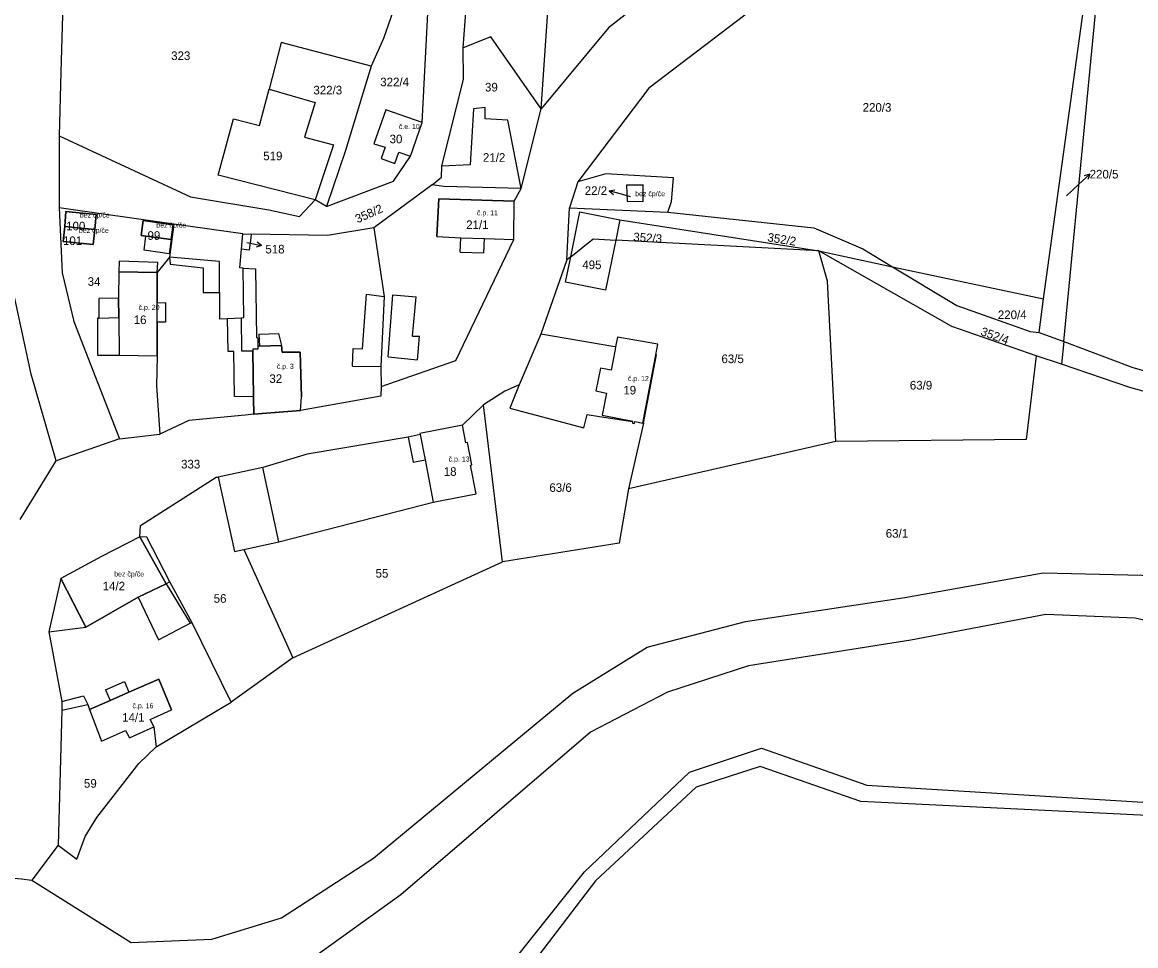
# Model space of a CAD drawing. Extents: x -880531 to -877616, y -1023932 to -1021350.
# Drawn here: x -878781.4 to -878561.2, y -1022509.8 to -1022327.2 of the extents above; entities that cross this region are included whole.
import ezdxf

# ---------------------------------------------------------------- set-up
doc = ezdxf.new("R2010")
doc.units = 0
for name, color, linetype in [('Definiční body', 7, 'Continuous'), ('Hranice parcel', 7, 'Continuous'), ('Parcelní čísla', 7, 'Continuous'), ('Polygon budovy', 7, 'Continuous'), ('Pop  PČ popisy', 7, 'Continuous'), ('Vnitřní kresba', 7, 'Continuous')]:
    doc.layers.add(name, color=color, linetype=linetype)

msp = doc.modelspace()

# ---------------------------------------------------------------- linework, layer by layer
at = {"layer": 'Hranice parcel'}
for p, q in [((-878579.47, -1022381.89), (-878569.16, -1022307.52)), ((-878702.35, -1022346.99), (-878701.15, -1022324.12)), ((-878694.27, -1022332.2), (-878693.64, -1022324.29)), ((-878682.77, -1022360.06), (-878678.8, -1022344.27)), ((-878704.66, -1022353.65), (-878702.35, -1022346.99)), ((-878774.14, -1022349.64), (-878774.16, -1022363.87)), ((-878700.4, -1022359.3), (-878711.92, -1022367.79)), ((-878671.6, -1022358.7), (-878673.23, -1022363.89)), ((-878721.25, -1022363.62), (-878723.5, -1022362.26)), ((-878751.45, -1022367.12), (-878774.16, -1022363.87)), ((-878673.72, -1022374.12), (-878673.23, -1022363.89)), ((-878673.23, -1022363.89), (-878653.77, -1022364.73)), ((-878773.06, -1022367.58), (-878767.11, -1022368.17)), ((-878737.82, -1022369.02), (-878751.45, -1022367.12)), ((-878663.25, -1022366.24), (-878664.07, -1022370.25)), ((-878663.25, -1022366.24), (-878623.93, -1022372.37)), ((-878738.07, -1022372.03), (-878737.82, -1022369.02)), ((-878737.82, -1022369.02), (-878736.18, -1022369.05)), ((-878736.18, -1022369.05), (-878736.26, -1022369.77)), ((-878623.93, -1022372.37), (-878664.07, -1022370.25)), ((-878738.41, -1022375.74), (-878738.07, -1022372.03)), ((-878623.93, -1022372.37), (-878609.33, -1022375.5)), ((-878673.72, -1022374.12), (-878678.87, -1022388.85)), ((-878672.98, -1022373.54), (-878673.72, -1022374.12)), ((-878609.33, -1022375.5), (-878579.47, -1022381.89)), ((-878580.3, -1022388.5), (-878579.47, -1022381.89)), ((-878678.87, -1022388.85), (-878683.16, -1022398.86)), ((-878655.76, -1022390.85), (-878663.73, -1022389.44)), ((-878580.3, -1022388.5), (-878575.47, -1022390.32)), ((-878575.47, -1022390.32), (-878575.9, -1022394.81)), ((-878575.9, -1022394.81), (-878580.9, -1022393.1)), ((-878735.65, -1022404.69), (-878735.69, -1022401.58)), ((-878690.21, -1022402.82), (-878694.41, -1022406.84)), ((-878686.48, -1022433.85), (-878690.21, -1022402.82)), ((-878658.6, -1022406.44), (-878661.53, -1022419.4)), ((-878762.25, -1022409.56), (-878774.74, -1022413.92)), ((-878762.25, -1022409.56), (-878754.24, -1022408.64)), ((-878620.57, -1022410.08), (-878661.53, -1022419.4)), ((-878781.84, -1022425.46), (-878774.74, -1022413.92)), ((-878737.66, -1022431.41), (-878727.94, -1022452.85)), ((-878727.94, -1022452.85), (-878686.48, -1022433.85)), ((-878727.94, -1022452.85), (-878740.13, -1022461.62)), ((-878754.97, -1022470.47), (-878740.13, -1022461.62)), ((-878773.64, -1022463.22), (-878774.32, -1022489.89)), ((-878774.32, -1022489.89), (-878779.59, -1022496.84))]:
    msp.add_line(p, q, dxfattribs=at)
for points in [[(-878589.21, -1022285.43), (-878614.84, -1022293.57), (-878633.22, -1022303.64), (-878648.06, -1022314.55), (-878665.5, -1022328.26), (-878678.8, -1022344.27)], [(-878678.8, -1022344.27), (-878675.7, -1022298.99), (-878693.21, -1022298.36)], [(-878772.79, -1022301.21), (-878773.84, -1022336.98), (-878774.14, -1022349.64)], [(-878609.56, -1022306.45), (-878614.79, -1022308.53), (-878635.51, -1022323.46), (-878657.51, -1022340.21), (-878671.6, -1022358.7)], [(-878575.47, -1022390.32), (-878567.58, -1022308.88), (-878569.16, -1022307.52)], [(-878707.2, -1022322.19), (-878709.98, -1022330.39), (-878712.42, -1022335.85)], [(-878678.8, -1022344.27), (-878688.78, -1022330.06), (-878694.27, -1022332.2)], [(-878712.42, -1022335.85), (-878730.27, -1022331.16), (-878732.62, -1022340.37)], [(-878698.46, -1022355.64), (-878694.2, -1022338.41), (-878694.27, -1022332.2)], [(-878712.42, -1022335.85), (-878717.5, -1022352.55), (-878721.25, -1022363.62)], [(-878723.5, -1022362.26), (-878742.72, -1022357.39), (-878739.68, -1022346.27), (-878734.53, -1022347.6), (-878732.62, -1022340.37)], [(-878732.62, -1022340.37), (-878723.52, -1022343.02), (-878725.66, -1022349.9), (-878719.9, -1022351.4), (-878723.5, -1022362.26)], [(-878702.35, -1022346.99), (-878709.57, -1022344.49), (-878711.91, -1022351.24), (-878709.69, -1022351.87), (-878710.48, -1022354.13), (-878707.77, -1022355.09), (-878706.97, -1022352.83), (-878704.66, -1022353.65)], [(-878682.77, -1022360.06), (-878685.43, -1022346.56), (-878689.88, -1022346.24), (-878689.9, -1022344.05), (-878692.19, -1022344.27), (-878692.85, -1022355.38), (-878698.46, -1022355.64)], [(-878774.14, -1022349.64), (-878748.17, -1022361.68), (-878732.67, -1022364.28), (-878726.64, -1022365.58), (-878723.5, -1022362.26)], [(-878721.25, -1022363.62), (-878708.06, -1022358.58), (-878704.66, -1022353.65)], [(-878700.4, -1022359.3), (-878698.51, -1022357.81), (-878698.46, -1022355.64)], [(-878653.77, -1022364.73), (-878653.07, -1022362.63), (-878652.68, -1022357.96), (-878666.04, -1022357.13), (-878671.6, -1022358.7)], [(-878682.77, -1022360.06), (-878698.08, -1022359.62), (-878700.4, -1022359.3)], [(-878710.46, -1022399.17), (-878695.68, -1022394.04), (-878684.22, -1022370.1), (-878684.16, -1022362.54), (-878682.77, -1022360.06)], [(-878774.16, -1022363.87), (-878773.56, -1022376.72), (-878771.27, -1022386.32), (-878762.25, -1022409.56)], [(-878773.06, -1022367.58), (-878772.81, -1022364.57), (-878766.82, -1022365.19), (-878767.11, -1022368.17)], [(-878672.98, -1022373.54), (-878671.2, -1022364.68), (-878663.25, -1022366.24)], [(-878653.77, -1022364.73), (-878624.87, -1022367.81), (-878615.19, -1022371.96), (-878609.33, -1022375.5)], [(-878767.11, -1022368.17), (-878767.41, -1022371.13), (-878773.34, -1022370.55), (-878773.06, -1022367.58)], [(-878757.35, -1022372.26), (-878756.99, -1022369.47), (-878757.92, -1022369.34), (-878757.52, -1022366.4), (-878751.61, -1022367.2), (-878752.01, -1022370.15), (-878752.39, -1022372.93), (-878757.35, -1022372.26)], [(-878751.45, -1022367.12), (-878752.35, -1022373.6), (-878754.77, -1022376.64)], [(-878711.92, -1022367.79), (-878721.1, -1022369.31), (-878736.18, -1022369.05)], [(-878711.92, -1022367.79), (-878709.9, -1022381.4), (-878710.51, -1022395.25), (-878710.46, -1022399.17)], [(-878774.74, -1022413.92), (-878779.71, -1022396.76), (-878785.9, -1022368.31)], [(-878736.26, -1022369.77), (-878736.56, -1022372.22), (-878738.07, -1022372.03)], [(-878664.07, -1022370.25), (-878666.08, -1022380.13), (-878673.99, -1022378.57), (-878672.98, -1022373.54)], [(-878620.57, -1022410.08), (-878622.18, -1022378.35), (-878623.93, -1022372.37)], [(-878580.9, -1022393.1), (-878597.59, -1022387.36), (-878623.93, -1022372.37)], [(-878754.77, -1022376.64), (-878754.67, -1022374.69), (-878762.26, -1022374.38), (-878762.32, -1022376.51), (-878762.39, -1022381.73), (-878766.33, -1022381.81), (-878766.34, -1022385.67)], [(-878738.06, -1022385.61), (-878737.65, -1022385.58), (-878737.77, -1022375.77), (-878738.41, -1022375.74)], [(-878609.33, -1022375.5), (-878596.58, -1022383.19), (-878582.14, -1022388.34), (-878580.3, -1022388.5)], [(-878766.34, -1022385.67), (-878766.59, -1022385.68), (-878766.55, -1022392.97), (-878762.28, -1022392.97), (-878754.76, -1022393.13), (-878754.89, -1022399.07), (-878754.24, -1022408.64)], [(-878735.69, -1022401.58), (-878735.69, -1022401.22), (-878735.88, -1022392.18), (-878738.02, -1022392.21), (-878738.06, -1022385.61)], [(-878663.73, -1022389.44), (-878664.11, -1022391.37), (-878664.66, -1022391.26), (-878678.87, -1022388.85)], [(-878658.6, -1022406.44), (-878655.98, -1022392.95), (-878656.15, -1022392.92), (-878655.76, -1022390.85)], [(-878575.47, -1022390.32), (-878561.81, -1022395.45), (-878519.45, -1022407.53), (-878480.63, -1022419.65)], [(-878580.9, -1022393.1), (-878582.9, -1022409.7), (-878620.57, -1022410.08)], [(-878431.64, -1022431.71), (-878476.27, -1022424.65), (-878519.53, -1022411.25), (-878562.4, -1022399.42), (-878575.9, -1022394.81)], [(-878683.16, -1022398.86), (-878686.03, -1022400.1), (-878690.21, -1022402.82)], [(-878683.16, -1022398.86), (-878685.01, -1022403.45), (-878670.39, -1022407.34), (-878669.75, -1022404.74), (-878667.29, -1022405.12), (-878660.73, -1022406.12), (-878660.79, -1022406.45)], [(-878710.46, -1022399.17), (-878710.55, -1022401.12), (-878726.45, -1022403.91), (-878735.65, -1022404.69)], [(-878735.65, -1022404.69), (-878737.39, -1022404.84), (-878748.51, -1022405.92), (-878754.24, -1022408.64)], [(-878694.41, -1022406.84), (-878702.8, -1022408.5), (-878702.76, -1022408.7), (-878705.12, -1022409.2), (-878725.11, -1022412.6), (-878733.89, -1022415.18), (-878742.68, -1022417.1)], [(-878737.66, -1022431.41), (-878730.68, -1022429.88), (-878700.15, -1022422.09), (-878691.7, -1022420.39), (-878692.82, -1022414.77), (-878692.53, -1022414.71), (-878693.41, -1022410.28), (-878693.71, -1022410.34), (-878694.41, -1022406.84)], [(-878660.79, -1022406.45), (-878660.36, -1022406.53), (-878660.28, -1022406.13)], [(-878660.28, -1022406.13), (-878658.73, -1022406.42), (-878658.6, -1022406.44)], [(-878758.2, -1022428.9), (-878758.09, -1022426.66), (-878743.07, -1022417.09), (-878742.68, -1022417.1)], [(-878742.68, -1022417.1), (-878739.45, -1022431.81), (-878737.66, -1022431.41)], [(-878661.53, -1022419.4), (-878663.38, -1022430.17), (-878686.48, -1022433.85)], [(-878758.2, -1022428.9), (-878765.76, -1022432.82), (-878773.82, -1022437.14)], [(-878752.28, -1022437.82), (-878756.8, -1022428.96), (-878758.2, -1022428.9)], [(-878779.59, -1022496.84), (-878759.93, -1022509.12), (-878743.95, -1022508.49), (-878730.15, -1022504.28), (-878711.96, -1022492.47), (-878672.55, -1022459.82), (-878657.85, -1022450.75), (-878638.42, -1022445.65), (-878606.87, -1022440.92), (-878579.56, -1022436.07), (-878560.03, -1022436.51), (-878534.07, -1022443.31), (-878452.29, -1022470.77)], [(-878773.82, -1022437.14), (-878776.19, -1022447.68), (-878773.63, -1022461.46), (-878773.64, -1022463.22)], [(-878752.28, -1022437.82), (-878753.01, -1022438.21), (-878758.51, -1022440.87), (-878768.9, -1022446.76), (-878773.82, -1022437.14)], [(-878740.13, -1022461.62), (-878747.87, -1022445.95), (-878752.28, -1022437.82)], [(-878108.11, -1022440.58), (-878152.15, -1022446.77), (-878167.86, -1022449.63), (-878217.16, -1022451.24), (-878301.33, -1022453.9), (-878333.67, -1022456.67), (-878366.21, -1022467.52), (-878407.13, -1022480.7), (-878435.64, -1022482.95), (-878455.12, -1022478.73), (-878537.04, -1022450.63), (-878561.34, -1022444.97), (-878578.99, -1022444.28), (-878605.69, -1022449.33), (-878637.81, -1022454.4), (-878653.86, -1022459.64), (-878669.06, -1022467.56), (-878706.56, -1022499.73), (-878724.15, -1022512.39), (-878736.44, -1022518.55), (-878757.9, -1022522.41)], [(-878773.64, -1022463.22), (-878768.49, -1022462.07), (-878768.18, -1022463.09), (-878765.77, -1022469.3), (-878761.06, -1022467.24), (-878760.21, -1022468.65), (-878755.46, -1022466.52), (-878754.97, -1022470.47)], [(-878774.32, -1022489.89), (-878770.65, -1022492.64), (-878769.02, -1022488.2), (-878766.68, -1022484.39), (-878758.38, -1022473.74), (-878754.97, -1022470.47)], [(-878757.9, -1022522.41), (-878743.38, -1022532.72), (-878730.23, -1022539.4), (-878709.85, -1022535.98), (-878694.32, -1022525.35), (-878670.27, -1022495.13), (-878649.48, -1022475.44), (-878635.27, -1022470.68), (-878614.41, -1022478.04), (-878543.73, -1022482.35), (-878506.92, -1022500.7), (-878475.11, -1022508.02), (-878399.08, -1022508.59), (-878373.94, -1022502.74), (-878346.19, -1022490.2), (-878334.94, -1022490.41), (-878279.22, -1022499.74), (-878220.51, -1022507.42), (-878194.43, -1022507.39), (-878145.84, -1022503.8), (-878124.82, -1022500.78)], [(-878125.35, -1022504.99), (-878146.35, -1022507.21), (-878194.02, -1022510.96), (-878220.76, -1022511.05), (-878280.27, -1022503.97), (-878335.4, -1022493.58), (-878344.86, -1022493.55), (-878371.73, -1022505.4), (-878399.1, -1022512.43), (-878475.7, -1022511.16), (-878508.77, -1022503.35), (-878545.47, -1022484.68), (-878615.6, -1022481.24), (-878635.5, -1022474.3), (-878648.14, -1022478.45), (-878668.08, -1022496.96), (-878691.68, -1022527.88), (-878708.19, -1022539.68), (-878731.2, -1022543.61), (-878748.07, -1022535.1), (-878763.51, -1022523.14)], [(-878789.71, -1022495.74), (-878787.92, -1022495.97), (-878781.61, -1022496.55), (-878779.59, -1022496.84)]]:
    msp.add_lwpolyline(points, dxfattribs=at)
at = {"layer": 'Polygon budovy'}
for points in [[(-878702.35, -1022346.99), (-878709.57, -1022344.49), (-878711.91, -1022351.24), (-878709.69, -1022351.87), (-878710.48, -1022354.13), (-878707.77, -1022355.09), (-878706.97, -1022352.83), (-878704.66, -1022353.65)], [(-878661.94, -1022359.37), (-878661.83, -1022362.54), (-878658.67, -1022362.63), (-878658.62, -1022359.35)], [(-878684.22, -1022370.1), (-878684.16, -1022362.54), (-878699.03, -1022362.08), (-878699.48, -1022369.54), (-878694.74, -1022369.8), (-878690.06, -1022369.93)], [(-878772.81, -1022364.57), (-878773.06, -1022367.58), (-878767.11, -1022368.17), (-878766.82, -1022365.19)], [(-878773.34, -1022370.55), (-878767.41, -1022371.13), (-878767.11, -1022368.17), (-878773.06, -1022367.58)], [(-878757.92, -1022369.34), (-878756.99, -1022369.47), (-878752.01, -1022370.15), (-878751.61, -1022367.2), (-878757.52, -1022366.4)], [(-878754.77, -1022386.5), (-878754.77, -1022382.62), (-878754.77, -1022376.64), (-878762.32, -1022376.51), (-878762.39, -1022381.73), (-878762.35, -1022385.53), (-878762.28, -1022392.97), (-878754.76, -1022393.13)], [(-878664.11, -1022391.37), (-878664.21, -1022391.9), (-878665.01, -1022395.96), (-878667.1, -1022395.55), (-878667.99, -1022400.08), (-878665.89, -1022400.49), (-878666.75, -1022404.86), (-878660.71, -1022406.04), (-878660.73, -1022406.12), (-878660.79, -1022406.45), (-878660.36, -1022406.53), (-878660.28, -1022406.13), (-878658.73, -1022406.42), (-878656.23, -1022393.32), (-878656.15, -1022392.92), (-878655.76, -1022390.85), (-878663.73, -1022389.44)], [(-878726.45, -1022403.91), (-878726.25, -1022401.24), (-878726.48, -1022392.42), (-878730.07, -1022392.4), (-878730.15, -1022391.08), (-878734.55, -1022391.24), (-878734.88, -1022391.25), (-878734.88, -1022391.82), (-878735.87, -1022391.84), (-878735.88, -1022392.18), (-878735.69, -1022401.22), (-878735.69, -1022401.58), (-878735.65, -1022404.69)], [(-878702.76, -1022408.7), (-878701.78, -1022413.71), (-878700.15, -1022422.09), (-878691.7, -1022420.39), (-878692.82, -1022414.77), (-878692.53, -1022414.71), (-878693.41, -1022410.28), (-878693.71, -1022410.34), (-878694.41, -1022406.84), (-878702.8, -1022408.5)], [(-878773.82, -1022437.14), (-878768.9, -1022446.76), (-878758.51, -1022440.87), (-878753.01, -1022438.21), (-878758.2, -1022428.9), (-878765.76, -1022432.82)], [(-878768.18, -1022463.09), (-878765.77, -1022469.3), (-878761.06, -1022467.24), (-878760.21, -1022468.65), (-878755.46, -1022466.52), (-878756.15, -1022465.01), (-878751.92, -1022463.1), (-878754.47, -1022457.09), (-878760.35, -1022459.64), (-878764.05, -1022461.31)]]:
    msp.add_lwpolyline(points, close=True, dxfattribs=at)
at = {"layer": 'Pop  PČ popisy'}
for p, q in [((-878574.9, -1022361.49), (-878572.53, -1022359.26)), ((-878572.53, -1022359.26), (-878570.335, -1022357.213)), ((-878570.335, -1022357.213), (-878571.409, -1022357.53)), ((-878570.335, -1022357.213), (-878570.726, -1022358.263)), ((-878665.345, -1022360.483), (-878664.244, -1022360.278)), ((-878662.46, -1022361.31), (-878665.345, -1022360.483)), ((-878665.345, -1022360.483), (-878664.52, -1022361.24)), ((-878661.18, -1022361.69), (-878662.46, -1022361.31)), ((-878737.06, -1022370.75), (-878734.114, -1022371.323)), ((-878734.114, -1022371.323), (-878735.193, -1022371.623)), ((-878734.114, -1022371.323), (-878735.002, -1022370.64))]:
    msp.add_line(p, q, dxfattribs=at)
at = {"layer": 'Vnitřní kresba'}
for p, q in [((-878661.94, -1022359.37), (-878658.62, -1022359.35)), ((-878658.67, -1022362.63), (-878658.62, -1022359.35)), ((-878661.94, -1022359.37), (-878661.83, -1022362.54)), ((-878699.48, -1022369.54), (-878699.03, -1022362.08)), ((-878699.03, -1022362.08), (-878684.16, -1022362.54)), ((-878661.83, -1022362.54), (-878658.67, -1022362.63)), ((-878752.01, -1022370.15), (-878756.99, -1022369.47)), ((-878699.48, -1022369.54), (-878694.74, -1022369.8)), ((-878694.86, -1022372.64), (-878694.74, -1022369.8)), ((-878694.74, -1022369.8), (-878690.06, -1022369.93)), ((-878690.14, -1022372.77), (-878690.06, -1022369.93)), ((-878690.06, -1022369.93), (-878684.22, -1022370.1)), ((-878672.98, -1022373.54), (-878668.52, -1022370.02)), ((-878668.52, -1022370.02), (-878664.07, -1022370.25)), ((-878742.44, -1022374.45), (-878752.35, -1022373.6)), ((-878752.35, -1022373.6), (-878752.2, -1022375.03)), ((-878742.45, -1022380.62), (-878742.44, -1022374.45)), ((-878694.86, -1022372.64), (-878690.14, -1022372.77)), ((-878762.32, -1022376.51), (-878754.77, -1022376.64)), ((-878754.77, -1022376.64), (-878754.77, -1022382.62)), ((-878752.2, -1022375.03), (-878745.67, -1022375.76)), ((-878745.67, -1022375.76), (-878745.66, -1022380.64)), ((-878737.77, -1022375.77), (-878735.29, -1022375.9)), ((-878735.29, -1022375.9), (-878735.1, -1022389.53)), ((-878745.66, -1022380.64), (-878742.45, -1022380.62)), ((-878742.45, -1022380.62), (-878742.45, -1022385.82)), ((-878714.17, -1022391.77), (-878713.34, -1022380.96)), ((-878713.34, -1022380.96), (-878709.9, -1022381.4)), ((-878709.09, -1022393.36), (-878708.14, -1022381.07)), ((-878708.14, -1022381.07), (-878703.55, -1022381.44)), ((-878762.35, -1022385.53), (-878762.39, -1022381.73)), ((-878754.77, -1022382.62), (-878753.15, -1022382.61)), ((-878754.77, -1022386.5), (-878754.77, -1022382.62)), ((-878753.15, -1022382.61), (-878753.13, -1022386.49)), ((-878704.25, -1022389.21), (-878703.55, -1022381.44)), ((-878766.34, -1022385.67), (-878762.35, -1022385.53)), ((-878762.35, -1022385.53), (-878762.28, -1022392.97)), ((-878742.45, -1022385.82), (-878740.84, -1022385.74)), ((-878740.84, -1022385.74), (-878738.06, -1022385.61)), ((-878740.75, -1022392.29), (-878740.84, -1022385.74)), ((-878753.13, -1022386.49), (-878754.77, -1022386.5)), ((-878754.77, -1022386.5), (-878754.76, -1022393.13)), ((-878735.1, -1022389.53), (-878734.89, -1022389.58)), ((-878734.89, -1022389.58), (-878734.88, -1022391.25)), ((-878734.63, -1022388.85), (-878730.75, -1022388.71)), ((-878734.63, -1022388.85), (-878734.55, -1022391.24)), ((-878730.75, -1022388.71), (-878730.15, -1022391.08)), ((-878704.25, -1022389.21), (-878702.89, -1022389.25)), ((-878703.26, -1022393.93), (-878702.89, -1022389.25)), ((-878739.59, -1022392.26), (-878740.75, -1022392.29)), ((-878739.45, -1022401.17), (-878739.59, -1022392.26)), ((-878735.87, -1022391.84), (-878735.88, -1022392.18)), ((-878734.88, -1022391.82), (-878735.87, -1022391.84)), ((-878734.55, -1022391.24), (-878734.88, -1022391.25)), ((-878734.88, -1022391.25), (-878734.88, -1022391.82)), ((-878734.55, -1022391.24), (-878730.15, -1022391.08)), ((-878730.15, -1022391.08), (-878730.07, -1022392.4)), ((-878730.07, -1022392.4), (-878726.48, -1022392.42)), ((-878716.15, -1022395.16), (-878716.01, -1022391.68)), ((-878716.01, -1022391.68), (-878714.17, -1022391.77)), ((-878664.21, -1022391.9), (-878665.01, -1022395.96)), ((-878664.11, -1022391.37), (-878664.21, -1022391.9)), ((-878726.48, -1022392.42), (-878726.25, -1022401.24)), ((-878709.09, -1022393.36), (-878703.26, -1022393.93)), ((-878658.73, -1022406.42), (-878656.23, -1022393.32)), ((-878656.23, -1022393.32), (-878656.15, -1022392.92)), ((-878716.15, -1022395.16), (-878710.51, -1022395.25)), ((-878667.1, -1022395.55), (-878667.99, -1022400.08)), ((-878665.01, -1022395.96), (-878667.1, -1022395.55)), ((-878735.69, -1022401.22), (-878739.45, -1022401.17)), ((-878667.99, -1022400.08), (-878665.89, -1022400.49)), ((-878665.89, -1022400.49), (-878666.75, -1022404.86)), ((-878726.45, -1022403.91), (-878726.25, -1022401.24)), ((-878666.75, -1022404.86), (-878660.71, -1022406.04)), ((-878660.71, -1022406.04), (-878660.73, -1022406.12)), ((-878705.12, -1022409.2), (-878704.15, -1022414.17)), ((-878702.76, -1022408.7), (-878701.78, -1022413.71)), ((-878704.15, -1022414.17), (-878701.78, -1022413.71)), ((-878701.78, -1022413.71), (-878700.15, -1022422.09)), ((-878730.68, -1022429.88), (-878733.89, -1022415.18)), ((-878758.2, -1022428.9), (-878753.01, -1022438.21)), ((-878753.01, -1022438.21), (-878748.24, -1022445.98)), ((-878758.51, -1022440.87), (-878754.48, -1022449.28)), ((-878776.19, -1022447.68), (-878768.9, -1022446.76)), ((-878754.48, -1022449.28), (-878748.24, -1022445.98)), ((-878748.24, -1022445.98), (-878747.87, -1022445.95)), ((-878764.98, -1022459.15), (-878761.26, -1022457.53)), ((-878761.26, -1022457.53), (-878760.35, -1022459.64)), ((-878760.35, -1022459.64), (-878754.47, -1022457.09)), ((-878754.47, -1022457.09), (-878751.92, -1022463.1)), ((-878773.63, -1022461.46), (-878769.37, -1022460.39)), ((-878769.37, -1022460.39), (-878768.49, -1022462.07)), ((-878764.98, -1022459.15), (-878764.05, -1022461.31)), ((-878764.05, -1022461.31), (-878760.35, -1022459.64)), ((-878768.18, -1022463.09), (-878764.05, -1022461.31)), ((-878756.15, -1022465.01), (-878751.92, -1022463.1)), ((-878756.15, -1022465.01), (-878755.46, -1022466.52))]:
    msp.add_line(p, q, dxfattribs=at)

# ---------------------------------------------------------------- texts
at = {"layer": 'Definiční body'}
for s, p in [('č.e. 10', (-878706.98, -1022348.28)), ('bez čp/če', (-878660.23, -1022361.57)), ('bez čp/če', (-878770.06, -1022365.8)), ('č.p. 11', (-878691.52, -1022365.35)), ('bez čp/če', (-878770.24, -1022368.82)), ('bez čp/če', (-878754.94, -1022367.79)), ('č.p. 20', (-878758.45, -1022384.05)), ('č.p. 3', (-878731.13, -1022395.7)), ('č.p. 12', (-878661.67, -1022398.12)), ('č.p. 13', (-878697.13, -1022414.04)), ('bez čp/če', (-878763.27, -1022436.76)), ('č.p. 16', (-878759.65, -1022462.81))]:
    msp.add_text(s, height=1, dxfattribs=at).set_placement(p)
at = {"layer": 'Parcelní čísla'}
for s, p in [('323', (-878752, -1022334.64)), ('322/4', (-878710.65, -1022339.83)), ('39', (-878689.93, -1022340.86)), ('322/3', (-878723.87, -1022341.44)), ('220/3', (-878615.24, -1022344.86)), ('30', (-878708.801, -1022351.1)), ('519', (-878733.79, -1022354.45)), ('21/2', (-878690.34, -1022354.76)), ('220/5', (-878570.34, -1022358.06)), ('22/2', (-878670.203, -1022361.31)), ('100', (-878772.769, -1022368.32)), ('21/1', (-878693.65, -1022368.06)), ('101', (-878773.402, -1022371.22)), ('99', (-878756.679, -1022370.19)), ('518', (-878733.37, -1022372.884)), ('495', (-878670.69, -1022375.98)), ('34', (-878768.52, -1022379.29)), ('16', (-878759.41, -1022386.85)), ('220/4', (-878588.5, -1022385.86)), ('63/5', (-878643.17, -1022394.57)), ('32', (-878732.58, -1022398.49)), ('63/9', (-878605.91, -1022399.79)), ('19', (-878662.57, -1022400.77)), ('333', (-878750.046, -1022415.4)), ('18', (-878698.09, -1022416.86)), ('63/6', (-878677.2, -1022420.03)), ('63/1', (-878610.67, -1022429.09)), ('55', (-878711.57, -1022436.99)), ('14/2', (-878765.55, -1022439.51)), ('56', (-878743.59, -1022441.96)), ('14/1', (-878761.7, -1022465.48)), ('59', (-878769.25, -1022478.53))]:
    msp.add_text(s, height=1.7, dxfattribs=at).set_placement(p)
for s, rotation, p in [('358/2', 24, (-878715.144, -1022366.936)), ('352/3', 356, (-878660.639, -1022370.437)), ('352/2', 351, (-878634.162, -1022370.479)), ('352/4', 340, (-878592.04, -1022388.988))]:
    msp.add_text(s, height=1.7, rotation=rotation, dxfattribs=at).set_placement(p)

doc.saveas('drawing.dxf')
